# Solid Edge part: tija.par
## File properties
Author: Ionut
Template: Normal.par
Last saved by: Ionut
Revision: 8
Application: Solid Edge
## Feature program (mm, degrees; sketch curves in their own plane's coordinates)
sketch for "unnamed Protrusion 1" plane through (0, 0, 0) normal (1, 0, 0) x-axis (0, 1, 0)
  circle centre (0, 0) radius 3
extrude "unnamed Protrusion 1" add finite 60 symmetric
sketch for "unnamed Cutout 1" plane through (30, 0, 0) normal (1, 0, 0) x-axis (0, 1, 0)
  line (1, 1.9425) -> (1, -1.8077)
extrude "unnamed Cutout 1" cut finite 5 along -normal
mirror "unnamed Mirror 1" of "unnamed Cutout 1" about plane through (0, 0, 0) normal (0, -1, 0)
extrude "unnamed Cutout 2" cut finite 5
sketch for "unnamed Hole 1" plane through (27.5, -1, 0) normal (0, -1, 0) x-axis (1, 0, 0)
  hole centre (0, 0) bore radius 1.5
hole "unnamed Hole 1" through
fillet "unnamed Round 1"
mirror "unnamed Mirror 2" of "unnamed Cutout 1", "unnamed Mirror 1", "unnamed Hole 1", "unnamed Round 1" about plane through (0, 0, 0) normal (1, 0, 0)
extrude "unnamed Cutout 3" cut finite 5
extrude "unnamed Cutout 4" cut finite 5
hole "unnamed Hole 2" through
fillet "unnamed Round 2"
fillet "unnamed Round 3"
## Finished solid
Body 1: solid body, 17 faces, 36 edges, 20 vertices.
  Faces by surface: plane 10, torus 4, cylinder 3
  Edges by curve: circle 16, line 12, intersection 8
Bounding box of the edges (mm; curved faces can reach further): 60.028 x 6.000 x 6.000, from (-30.014, -3, -3) to (30.014, 3, 3).
Cylindrical faces by radius (mm): R1.5 x2, R3 x1
Toroidal faces (ring radius, tube radius in mm): R1 r2 x4
Planar faces by outward normal: +x 3, +y 2, -x 3, -y 2
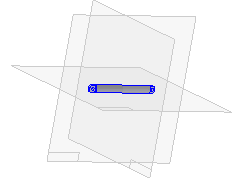
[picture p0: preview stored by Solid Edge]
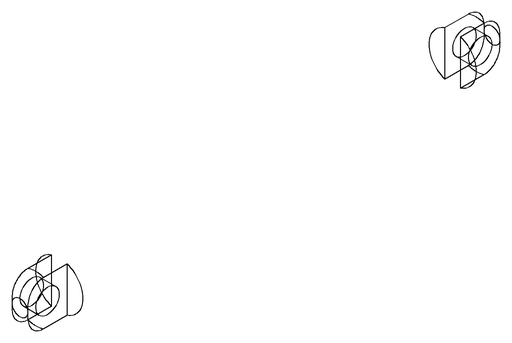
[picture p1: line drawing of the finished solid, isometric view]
